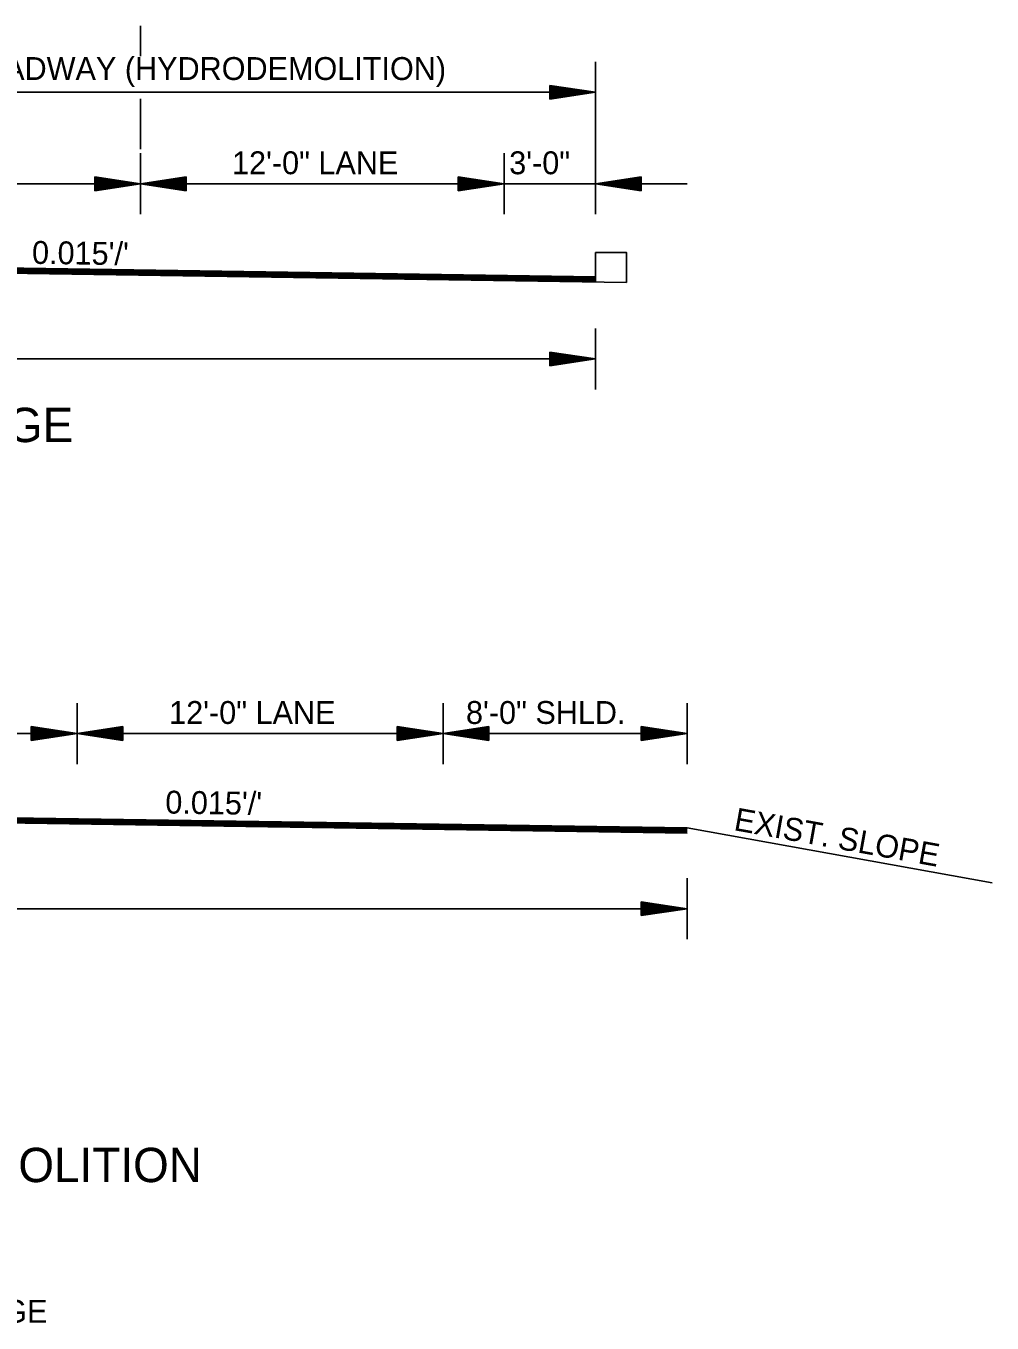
# Model space of a CAD drawing. Extents: x 549600 to 1930787, y -1955432 to 596640.
# Drawn here: x 551674.6 to 551991.3, y -1947601.9 to -1947176.8 of the extents above; entities that cross this region are included whole.
import ezdxf

# ---------------------------------------------------------------- set-up
doc = ezdxf.new("R2010")
doc.units = 0
doc.layers.add('R_Border', color=7, linetype='Continuous')
doc.layers.add('S_AREA_CALC', color=7, linetype='Continuous')

msp = doc.modelspace()

# ---------------------------------------------------------------- linework, layer by layer
at = {"layer": 'R_Border'}
for p, q in [((551861.35, -1947228.55), (551891.35, -1947228.55)), ((551891.35, -1947439.63), (551991.35, -1947457.63))]:
    msp.add_line(p, q, dxfattribs=at)
msp.add_lwpolyline([(551861.35, -1947260.53), (551861.35, -1947251.09), (551871.51, -1947251.09), (551871.51, -1947260.88)], dxfattribs=at)
at = {"layer": 'S_AREA_CALC'}
for p, q in [((551712.14, -1947186.68), (551712.14, -1947176.81)), ((551861.35, -1947238.55), (551861.35, -1947188.55)), ((551861.35, -1947198.55), (551561.35, -1947198.55)), ((551846.35, -1947196.3), (551861.35, -1947198.55)), ((551846.35, -1947200.8), (551846.35, -1947196.3)), ((551846.35, -1947196.67), (551858.84, -1947198.55)), ((551846.35, -1947197.05), (551856.26, -1947198.55)), ((551846.35, -1947197.43), (551853.76, -1947198.55)), ((551846.35, -1947197.81), (551851.22, -1947198.55)), ((551846.35, -1947198.19), (551848.72, -1947198.55)), ((551846.35, -1947200.8), (551861.35, -1947198.55)), ((551846.35, -1947199.27), (551851.22, -1947198.55)), ((551846.35, -1947200.04), (551856.26, -1947198.55)), ((551846.35, -1947200.42), (551858.84, -1947198.55)), ((551846.35, -1947199.66), (551853.76, -1947198.55)), ((551846.35, -1947198.9), (551848.72, -1947198.55)), ((551712.14, -1947217.21), (551712.14, -1947200.71)), ((551712.14, -1947218.55), (551712.14, -1947238.55)), ((551831.35, -1947218.55), (551831.35, -1947238.55)), ((551561.35, -1947228.55), (551861.35, -1947228.55)), ((551697.14, -1947226.3), (551712.14, -1947228.55)), ((551697.14, -1947230.8), (551697.14, -1947226.3)), ((551697.14, -1947226.67), (551709.63, -1947228.55)), ((551697.14, -1947227.05), (551707.05, -1947228.55)), ((551697.14, -1947227.43), (551704.56, -1947228.55)), ((551697.14, -1947227.81), (551702.01, -1947228.55)), ((551697.14, -1947228.19), (551699.51, -1947228.55)), ((551697.14, -1947230.8), (551712.14, -1947228.55)), ((551697.14, -1947229.27), (551702.01, -1947228.55)), ((551697.14, -1947230.04), (551707.05, -1947228.55)), ((551697.14, -1947230.42), (551709.63, -1947228.55)), ((551697.14, -1947229.66), (551704.56, -1947228.55)), ((551697.14, -1947228.9), (551699.51, -1947228.55)), ((551727.14, -1947226.3), (551712.14, -1947228.55)), ((551727.14, -1947230.8), (551712.14, -1947228.55)), ((551727.14, -1947226.67), (551714.64, -1947228.55)), ((551727.14, -1947230.42), (551714.64, -1947228.55)), ((551727.14, -1947227.05), (551717.22, -1947228.55)), ((551727.14, -1947230.04), (551717.22, -1947228.55)), ((551727.14, -1947227.43), (551719.72, -1947228.55)), ((551727.14, -1947229.66), (551719.72, -1947228.55)), ((551727.14, -1947227.82), (551722.26, -1947228.55)), ((551727.14, -1947229.28), (551722.26, -1947228.55)), ((551727.14, -1947228.19), (551724.77, -1947228.55)), ((551727.14, -1947228.9), (551724.77, -1947228.55)), ((551727.14, -1947226.3), (551727.14, -1947230.8)), ((551816.35, -1947226.3), (551831.35, -1947228.55)), ((551816.35, -1947230.8), (551816.35, -1947226.3)), ((551816.35, -1947226.67), (551828.84, -1947228.55)), ((551816.35, -1947227.05), (551826.26, -1947228.55)), ((551816.35, -1947227.43), (551823.76, -1947228.55)), ((551816.35, -1947227.81), (551821.22, -1947228.55)), ((551816.35, -1947228.19), (551818.72, -1947228.55)), ((551816.35, -1947230.8), (551831.35, -1947228.55)), ((551816.35, -1947229.27), (551821.22, -1947228.55)), ((551816.35, -1947230.04), (551826.26, -1947228.55)), ((551816.35, -1947230.42), (551828.84, -1947228.55)), ((551816.35, -1947229.66), (551823.76, -1947228.55)), ((551816.35, -1947228.9), (551818.72, -1947228.55)), ((551876.35, -1947226.3), (551861.35, -1947228.55)), ((551876.35, -1947230.8), (551861.35, -1947228.55)), ((551876.35, -1947226.67), (551863.85, -1947228.55)), ((551876.35, -1947230.42), (551863.85, -1947228.55)), ((551876.35, -1947227.05), (551866.43, -1947228.55)), ((551876.35, -1947230.04), (551866.43, -1947228.55)), ((551876.35, -1947227.43), (551868.93, -1947228.55)), ((551876.35, -1947229.66), (551868.93, -1947228.55)), ((551876.35, -1947227.82), (551871.47, -1947228.55)), ((551876.35, -1947229.28), (551871.47, -1947228.55)), ((551876.35, -1947228.19), (551873.98, -1947228.55)), ((551876.35, -1947228.9), (551873.98, -1947228.55)), ((551876.35, -1947226.3), (551876.35, -1947230.8)), ((551861.35, -1947275.96), (551861.35, -1947295.96)), ((551846.35, -1947283.71), (551861.35, -1947285.96)), ((551846.35, -1947283.71), (551846.35, -1947288.21)), ((551846.35, -1947284.08), (551858.84, -1947285.96)), ((551846.35, -1947284.46), (551856.26, -1947285.96)), ((551846.35, -1947284.84), (551853.76, -1947285.96)), ((551241.35, -1947285.96), (551861.35, -1947285.96)), ((551846.35, -1947285.23), (551851.22, -1947285.96)), ((551846.35, -1947285.6), (551848.72, -1947285.96)), ((551846.35, -1947288.21), (551861.35, -1947285.96)), ((551846.35, -1947286.69), (551851.22, -1947285.96)), ((551846.35, -1947287.45), (551856.26, -1947285.96)), ((551846.35, -1947287.83), (551858.84, -1947285.96)), ((551846.35, -1947287.07), (551853.76, -1947285.96)), ((551846.35, -1947286.31), (551848.72, -1947285.96)), ((551691.35, -1947398.7), (551691.35, -1947418.7)), ((551811.35, -1947398.7), (551811.35, -1947418.7)), ((551891.35, -1947398.7), (551891.35, -1947418.7)), ((551676.35, -1947406.45), (551691.35, -1947408.7)), ((551676.35, -1947406.45), (551676.35, -1947410.95)), ((551676.35, -1947406.82), (551688.84, -1947408.7)), ((551676.35, -1947407.21), (551686.26, -1947408.7)), ((551676.35, -1947407.58), (551683.76, -1947408.7)), ((551676.35, -1947407.97), (551681.22, -1947408.7)), ((551676.35, -1947408.35), (551678.72, -1947408.7)), ((551706.35, -1947406.45), (551691.35, -1947408.7)), ((551706.35, -1947406.82), (551693.85, -1947408.7)), ((551706.35, -1947407.21), (551696.43, -1947408.7)), ((551706.35, -1947407.58), (551698.93, -1947408.7)), ((551706.35, -1947407.96), (551701.47, -1947408.7)), ((551706.35, -1947408.35), (551703.98, -1947408.7)), ((551706.35, -1947410.95), (551706.35, -1947406.45)), ((551796.35, -1947406.45), (551811.35, -1947408.7)), ((551796.35, -1947406.45), (551796.35, -1947410.95)), ((551796.35, -1947406.82), (551808.84, -1947408.7)), ((551796.35, -1947407.21), (551806.26, -1947408.7)), ((551796.35, -1947407.58), (551803.76, -1947408.7)), ((551796.35, -1947407.97), (551801.22, -1947408.7)), ((551796.35, -1947408.35), (551798.72, -1947408.7)), ((551826.35, -1947406.45), (551811.35, -1947408.7)), ((551826.35, -1947406.82), (551813.85, -1947408.7)), ((551826.35, -1947407.21), (551816.43, -1947408.7)), ((551826.35, -1947407.58), (551818.93, -1947408.7)), ((551826.35, -1947407.96), (551821.47, -1947408.7)), ((551826.35, -1947408.35), (551823.98, -1947408.7)), ((551826.35, -1947410.95), (551826.35, -1947406.45)), ((551876.35, -1947406.45), (551891.35, -1947408.7)), ((551876.35, -1947406.45), (551876.35, -1947410.95)), ((551876.35, -1947406.82), (551888.84, -1947408.7)), ((551876.35, -1947407.21), (551886.26, -1947408.7)), ((551876.35, -1947407.58), (551883.76, -1947408.7)), ((551876.35, -1947407.97), (551881.22, -1947408.7)), ((551876.35, -1947408.35), (551878.72, -1947408.7)), ((551211.35, -1947408.7), (551891.35, -1947408.7)), ((551676.35, -1947410.95), (551691.35, -1947408.7)), ((551676.35, -1947409.43), (551681.22, -1947408.7)), ((551676.35, -1947410.19), (551686.26, -1947408.7)), ((551676.35, -1947410.57), (551688.84, -1947408.7)), ((551676.35, -1947409.82), (551683.76, -1947408.7)), ((551676.35, -1947409.05), (551678.72, -1947408.7)), ((551706.35, -1947410.95), (551691.35, -1947408.7)), ((551706.35, -1947410.57), (551693.85, -1947408.7)), ((551706.35, -1947410.19), (551696.43, -1947408.7)), ((551706.35, -1947409.82), (551698.93, -1947408.7)), ((551706.35, -1947409.43), (551701.47, -1947408.7)), ((551706.35, -1947409.05), (551703.98, -1947408.7)), ((551796.35, -1947410.95), (551811.35, -1947408.7)), ((551796.35, -1947409.43), (551801.22, -1947408.7)), ((551796.35, -1947410.19), (551806.26, -1947408.7)), ((551796.35, -1947410.57), (551808.84, -1947408.7)), ((551796.35, -1947409.82), (551803.76, -1947408.7)), ((551796.35, -1947409.05), (551798.72, -1947408.7)), ((551826.35, -1947410.95), (551811.35, -1947408.7)), ((551826.35, -1947410.57), (551813.85, -1947408.7)), ((551826.35, -1947410.19), (551816.43, -1947408.7)), ((551826.35, -1947409.82), (551818.93, -1947408.7)), ((551826.35, -1947409.43), (551821.47, -1947408.7)), ((551826.35, -1947409.05), (551823.98, -1947408.7)), ((551876.35, -1947410.95), (551891.35, -1947408.7)), ((551876.35, -1947409.43), (551881.22, -1947408.7)), ((551876.35, -1947410.19), (551886.26, -1947408.7)), ((551876.35, -1947410.57), (551888.84, -1947408.7)), ((551876.35, -1947409.82), (551883.76, -1947408.7)), ((551876.35, -1947409.05), (551878.72, -1947408.7)), ((551891.35, -1947456.11), (551891.35, -1947476.11)), ((551211.35, -1947466.11), (551891.35, -1947466.11)), ((551876.35, -1947463.86), (551891.35, -1947466.11)), ((551876.35, -1947463.86), (551876.35, -1947468.36)), ((551876.35, -1947464.23), (551888.84, -1947466.11)), ((551876.35, -1947464.62), (551886.26, -1947466.11)), ((551876.35, -1947464.99), (551883.76, -1947466.11)), ((551876.35, -1947465.38), (551881.22, -1947466.11)), ((551876.35, -1947465.76), (551878.72, -1947466.11)), ((551876.35, -1947468.36), (551891.35, -1947466.11)), ((551876.35, -1947466.84), (551881.22, -1947466.11)), ((551876.35, -1947467.6), (551886.26, -1947466.11)), ((551876.35, -1947467.98), (551888.84, -1947466.11)), ((551876.35, -1947467.23), (551883.76, -1947466.11)), ((551876.35, -1947466.46), (551878.72, -1947466.11))]:
    msp.add_line(p, q, dxfattribs=at)
for points in [[(551241.35, -1947259.03), (551551.35, -1947254.38), (551861.35, -1947259.03)], [(551241.35, -1947259.33), (551551.35, -1947254.68), (551861.35, -1947259.33)], [(551241.35, -1947259.63), (551551.35, -1947254.98), (551861.35, -1947259.63)], [(551241.35, -1947259.93), (551551.35, -1947255.28), (551861.35, -1947259.93)], [(551231.18, -1947260.88), (551551.35, -1947256.08), (551871.51, -1947260.88)], [(551241.35, -1947260.23), (551551.35, -1947255.58), (551861.35, -1947260.23)], [(551241.35, -1947260.53), (551551.35, -1947255.88), (551861.35, -1947260.53)], [(551211.35, -1947439.63), (551551.35, -1947434.53), (551891.35, -1947439.63)], [(551211.35, -1947439.93), (551551.35, -1947434.83), (551891.35, -1947439.93)], [(551211.35, -1947440.23), (551551.35, -1947435.13), (551891.35, -1947440.23)], [(551211.35, -1947440.53), (551551.35, -1947435.43), (551891.35, -1947440.53)], [(551211.35, -1947440.83), (551551.35, -1947435.73), (551891.35, -1947440.83)], [(551211.35, -1947441.13), (551551.35, -1947436.03), (551891.35, -1947441.13)], [(551211.35, -1947441.33), (551551.35, -1947436.23), (551891.35, -1947441.33)]]:
    msp.add_lwpolyline(points, dxfattribs=at)

# ---------------------------------------------------------------- texts
at = {"layer": 'R_Border'}
for s, height, p in [('30\'-0" CLEAR ROADWAY (HYDRODEMOLITION)', 7.5, (551587.86, -1947194.52)), ('60 FT. CLEAR ROADWAY BRIDGE - HYDRODEMOLITION', 11.25, (551329.4, -1947555.72)), ('- BR NO. 05211 - HWY. 79:  ARKANSAS RIVER BRIDGE', 7.5, (551423.6, -1947601.8))]:
    msp.add_text(s, height=height, dxfattribs=at).set_placement(p)
msp.add_text('EXIST. SLOPE', height=7.5, rotation=349.796, dxfattribs=at).set_placement((551906.42, -1947440.34))
at = {"layer": 'S_AREA_CALC'}
for s, height, p in [('12\'-0" LANE', 7.5, (551742.17, -1947225.41)), ('3\'-0"', 7.5, (551833.04, -1947225.41)), ('4 LANE BRIDGE - ARKANSAS RIVER BRIDGE', 11.25, (551369.06, -1947313.2)), ('12\'-0" LANE', 7.5, (551721.55, -1947405.56)), ('8\'-0" SHLD.', 7.5, (551818.87, -1947405.56))]:
    msp.add_text(s, height=height, dxfattribs=at).set_placement(p)
for p in [(551676.56, -1947254.76), (551720.26, -1947434.91)]:
    msp.add_text("0.015'/'", height=7.5, rotation=359.1406, dxfattribs=at).set_placement(p)

doc.saveas('drawing.dxf')
